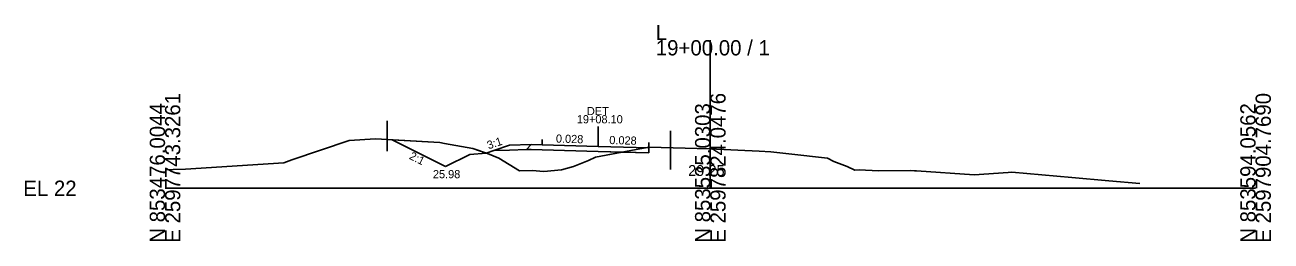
# Model space of a CAD drawing. Extents: x -26 to 1203, y -10 to 9526.
# Drawn here: x -25.7 to 202.8, y 8990.3 to 9030 of the extents above; entities that cross this region are included whole.
import ezdxf

# ---------------------------------------------------------------- set-up
doc = ezdxf.new("R2010")
doc.units = 0
for name, color, linetype in [('Exist Cross Section Cell', 7, 'Continuous'), ('Exist XS Center Line Elevation Label', 7, 'Continuous'), ('Exist XS Ground Line', 7, 'Continuous'), ('Prop XS Alignment Label', 7, 'Continuous'), ('Prop XS DDE', 7, 'Continuous'), ('Prop XS DDE Earthwork Shape', 7, 'Continuous'), ('Prop XS DDE Elevations', 7, 'Continuous'), ('Prop XS DDE Slope Text', 7, 'Continuous'), ('Prop XS Earthwork Shape', 7, 'Continuous'), ('Prop XS EOT Tick Mark', 7, 'Continuous'), ('Prop XS Exc Vertical Line 1', 7, 'Continuous'), ('Prop XS Exc Vertical Line 2', 7, 'Continuous'), ('Prop XS Finish Grade', 7, 'Continuous'), ('Prop XS Finish Grade Earthwork', 7, 'Continuous'), ('Prop XS Finish Grade Paved Shoulder', 7, 'Continuous'), ('Prop XS Finish Grade Pavement', 7, 'Continuous'), ('Prop XS Pvmt Edge Slope', 7, 'Continuous'), ('Prop XS SE Text', 7, 'Continuous'), ('Prop XS Side Slope Text', 7, 'Continuous'), ('Prop XS Station Labels', 7, 'Continuous'), ('Prop XS Subgrade Earthwork', 7, 'Continuous'), ('Scratch_Level_1', 7, 'Continuous')]:
    doc.layers.add(name, color=color, linetype=linetype)

msp = doc.modelspace()

# ---------------------------------------------------------------- linework, layer by layer
at = {"layer": 'Exist Cross Section Cell'}
for p, q in [((100, 9000), (100, 9027.17)), ((0, 9000), (100, 9000)), ((100, 9000), (200, 9000))]:
    msp.add_line(p, q, dxfattribs=at)
at = {"layer": 'Exist XS Ground Line'}
for p, q in [((33.74, 9008.75), (38.63, 9009.06)), ((38.63, 9009.06), (50.4, 9008.37)), ((23.28, 9005.23), (33.74, 9008.75)), ((50.4, 9008.37), (51.27, 9008.23)), ((51.27, 9008.23), (56.44, 9007.27)), ((56.44, 9007.27), (59.11, 9006.39)), ((78.96, 9005.69), (85.44, 9006.93)), ((85.44, 9006.93), (88.8, 9007.53)), ((88.8, 9007.53), (97.62, 9007.32)), ((97.62, 9007.32), (99.87, 9007.26)), ((99.87, 9007.26), (108.97, 9006.82)), ((108.97, 9006.82), (111.07, 9006.71)), ((111.07, 9006.71), (114.42, 9006.29)), ((3.76, 9003.53), (21.77, 9004.69)), ((21.77, 9004.69), (23.28, 9005.23)), ((59.11, 9006.39), (61.2, 9005.51)), ((61.2, 9005.51), (65.02, 9003.19)), ((74.93, 9004.02), (77.69, 9005.1)), ((77.69, 9005.1), (78.96, 9005.69)), ((114.42, 9006.29), (121.48, 9005.53)), ((121.48, 9005.53), (122.67, 9004.88)), ((122.67, 9004.88), (125.12, 9003.98)), ((0, 9003.35), (1.5, 9003.41)), ((1.5, 9003.41), (3.76, 9003.53)), ((65.02, 9003.19), (67.32, 9003.24)), ((67.32, 9003.24), (69.46, 9003.07)), ((69.46, 9003.07), (72.73, 9003.38)), ((72.73, 9003.38), (74.93, 9004.02)), ((125.12, 9003.98), (126.52, 9003.34)), ((126.52, 9003.34), (127.27, 9003.35)), ((127.27, 9003.35), (130.85, 9003.19)), ((130.85, 9003.19), (136.78, 9003.25)), ((136.78, 9003.25), (137.46, 9003.21)), ((137.46, 9003.21), (137.8, 9003.2)), ((137.8, 9003.2), (148.41, 9002.47)), ((148.41, 9002.47), (154.65, 9002.88)), ((154.65, 9002.88), (155.29, 9002.96)), ((155.29, 9002.96), (166.27, 9001.98)), ((166.27, 9001.98), (173.06, 9001.35)), ((173.06, 9001.35), (178.76, 9000.89))]:
    msp.add_line(p, q, dxfattribs=at)
at = {"layer": 'Prop XS DDE'}
for p, q in [((41.64, 9008.88), (51.45, 9003.98)), ((51.45, 9003.98), (55.91, 9006.21)), ((55.91, 9006.21), (58.91, 9006.46))]:
    msp.add_line(p, q, dxfattribs=at)
at = {"layer": 'Prop XS DDE Earthwork Shape'}
for p, q in [((50.4, 9008.37), (41.64, 9008.88)), ((41.64, 9008.88), (51.45, 9003.98)), ((51.27, 9008.23), (50.4, 9008.37)), ((56.44, 9007.27), (51.27, 9008.23)), ((58.91, 9006.46), (56.44, 9007.27)), ((51.45, 9003.98), (55.91, 9006.21)), ((55.91, 9006.21), (58.91, 9006.46))]:
    msp.add_line(p, q, dxfattribs=at)
at = {"layer": 'Prop XS Earthwork Shape'}
for points in [[(63.16, 9007.01), (60.3, 9006.92), (58.91, 9006.46), (59.11, 9006.39), (61.2, 9005.51), (65.02, 9003.19), (67.32, 9003.24), (69.46, 9003.07), (72.73, 9003.38), (74.93, 9004.02), (77.69, 9005.1), (78.96, 9005.69), (83.83, 9006.62), (79.41, 9006.75), (69.16, 9007.03), (67.16, 9007.09), (66.27, 9007.11)], [(88.73, 9006.49), (83.83, 9006.62), (85.44, 9006.93), (88.73, 9007.51)]]:
    msp.add_lwpolyline(points, close=True, dxfattribs=at)
at = {"layer": 'Prop XS EOT Tick Mark'}
for p, q in [((69.16, 9007.95), (69.16, 9008.95)), ((88.73, 9007.4), (88.73, 9008.4))]:
    msp.add_line(p, q, dxfattribs=at)
at = {"layer": 'Prop XS Exc Vertical Line 1'}
msp.add_line((40.72, 9012.38), (40.72, 9006.8), dxfattribs=at)
at = {"layer": 'Prop XS Exc Vertical Line 2'}
msp.add_line((92.72, 9010.52), (92.72, 9003.45), dxfattribs=at)
at = {"layer": 'Prop XS Finish Grade'}
for p, q in [((63.16, 9007.88), (60.3, 9006.92)), ((67.16, 9008), (63.16, 9007.88))]:
    msp.add_line(p, q, dxfattribs=at)
at = {"layer": 'Prop XS Finish Grade Earthwork'}
msp.add_line((58.91, 9006.46), (60.3, 9006.92), dxfattribs=at)
at = {"layer": 'Prop XS Finish Grade Paved Shoulder'}
msp.add_line((69.16, 9007.95), (67.16, 9008), dxfattribs=at)
at = {"layer": 'Prop XS Finish Grade Pavement'}
for p, q in [((69.16, 9007.95), (79.41, 9007.66)), ((79.41, 9007.66), (88.73, 9007.4))]:
    msp.add_line(p, q, dxfattribs=at)
at = {"layer": 'Prop XS Pvmt Edge Slope'}
msp.add_line((67.16, 9008), (66.27, 9007.11), dxfattribs=at)
at = {"layer": 'Prop XS Side Slope Text'}
msp.add_line((79.41, 9007.66), (79.41, 9011.32), dxfattribs=at)
at = {"layer": 'Prop XS Subgrade Earthwork'}
for p, q in [((63.16, 9007.01), (60.3, 9006.92)), ((66.27, 9007.11), (63.16, 9007.01)), ((67.16, 9007.09), (66.27, 9007.11)), ((69.16, 9007.03), (67.16, 9007.09)), ((79.41, 9006.75), (69.16, 9007.03)), ((88.73, 9006.49), (79.41, 9006.75)), ((88.73, 9007.51), (88.73, 9006.49))]:
    msp.add_line(p, q, dxfattribs=at)
at = {"layer": 'Scratch_Level_1'}
for points in [[(63.16, 9007.01), (60.3, 9006.92), (63.16, 9007.88), (67.16, 9008), (66.27, 9007.11)], [(67.16, 9008), (63.16, 9007.88), (60.3, 9006.92), (63.16, 9007.01), (66.27, 9007.11)]]:
    msp.add_lwpolyline(points, close=True, dxfattribs=at)

# ---------------------------------------------------------------- texts
at = {"layer": 'Exist Cross Section Cell'}
for s, p in [('L', (90, 9027.17)), ('19+00.00 / 1', (90, 9024.37)), ('EL 22', (-26, 8998.6))]:
    msp.add_text(s, height=2.8, dxfattribs=at).set_placement(p)
for s, p in [('E 2597743.3261', (2.8, 8990)), ('E 2597824.0476', (102.8, 8990)), ('E 2597904.7690', (202.8, 8990)), ('N 853476.0044', (0, 8990)), ('N 853535.0303', (100, 8990)), ('N 853594.0562', (200, 8990))]:
    msp.add_text(s, height=2.8, rotation=90, dxfattribs=at).set_placement(p)
at = {"layer": 'Exist XS Center Line Elevation Label'}
msp.add_text('29.25', height=2, dxfattribs=at).set_placement((95.93, 9002.25))
at = {"layer": 'Prop XS Alignment Label'}
msp.add_text('DET', height=1.5, dxfattribs=at).set_placement((77.37, 9013.41))
at = {"layer": 'Prop XS DDE Elevations'}
msp.add_text('25.98', height=1.5, dxfattribs=at).set_placement((49.13, 9001.84))
at = {"layer": 'Prop XS DDE Slope Text'}
msp.add_text('2:1', height=1.5, rotation=333.4349, dxfattribs=at).set_placement((44.66, 9005.44))
at = {"layer": 'Prop XS SE Text'}
for rotation, p in [(358.4069, (71.67, 9008.38)), (358.4098, (81.46, 9008.11))]:
    msp.add_text('0.028', height=1.5, rotation=rotation, dxfattribs=at).set_placement(p)
at = {"layer": 'Prop XS Side Slope Text'}
msp.add_text('3:1', height=1.5, rotation=18.4349, dxfattribs=at).set_placement((59.34, 9007.13))
at = {"layer": 'Prop XS Station Labels'}
msp.add_text('19+08.10', height=1.5, dxfattribs=at).set_placement((75.52, 9011.91))

doc.saveas('drawing.dxf')
